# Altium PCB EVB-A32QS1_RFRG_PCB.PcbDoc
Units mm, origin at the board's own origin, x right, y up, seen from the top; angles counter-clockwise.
Board outline 51 x 34 mm, 4 copper layers (L1 (Signal), L2 (GND), L3 (PWR), L4 (Signal)), stack 1.586 mm thick; 35 components, 27 nets, 143 pads, 70 vias.
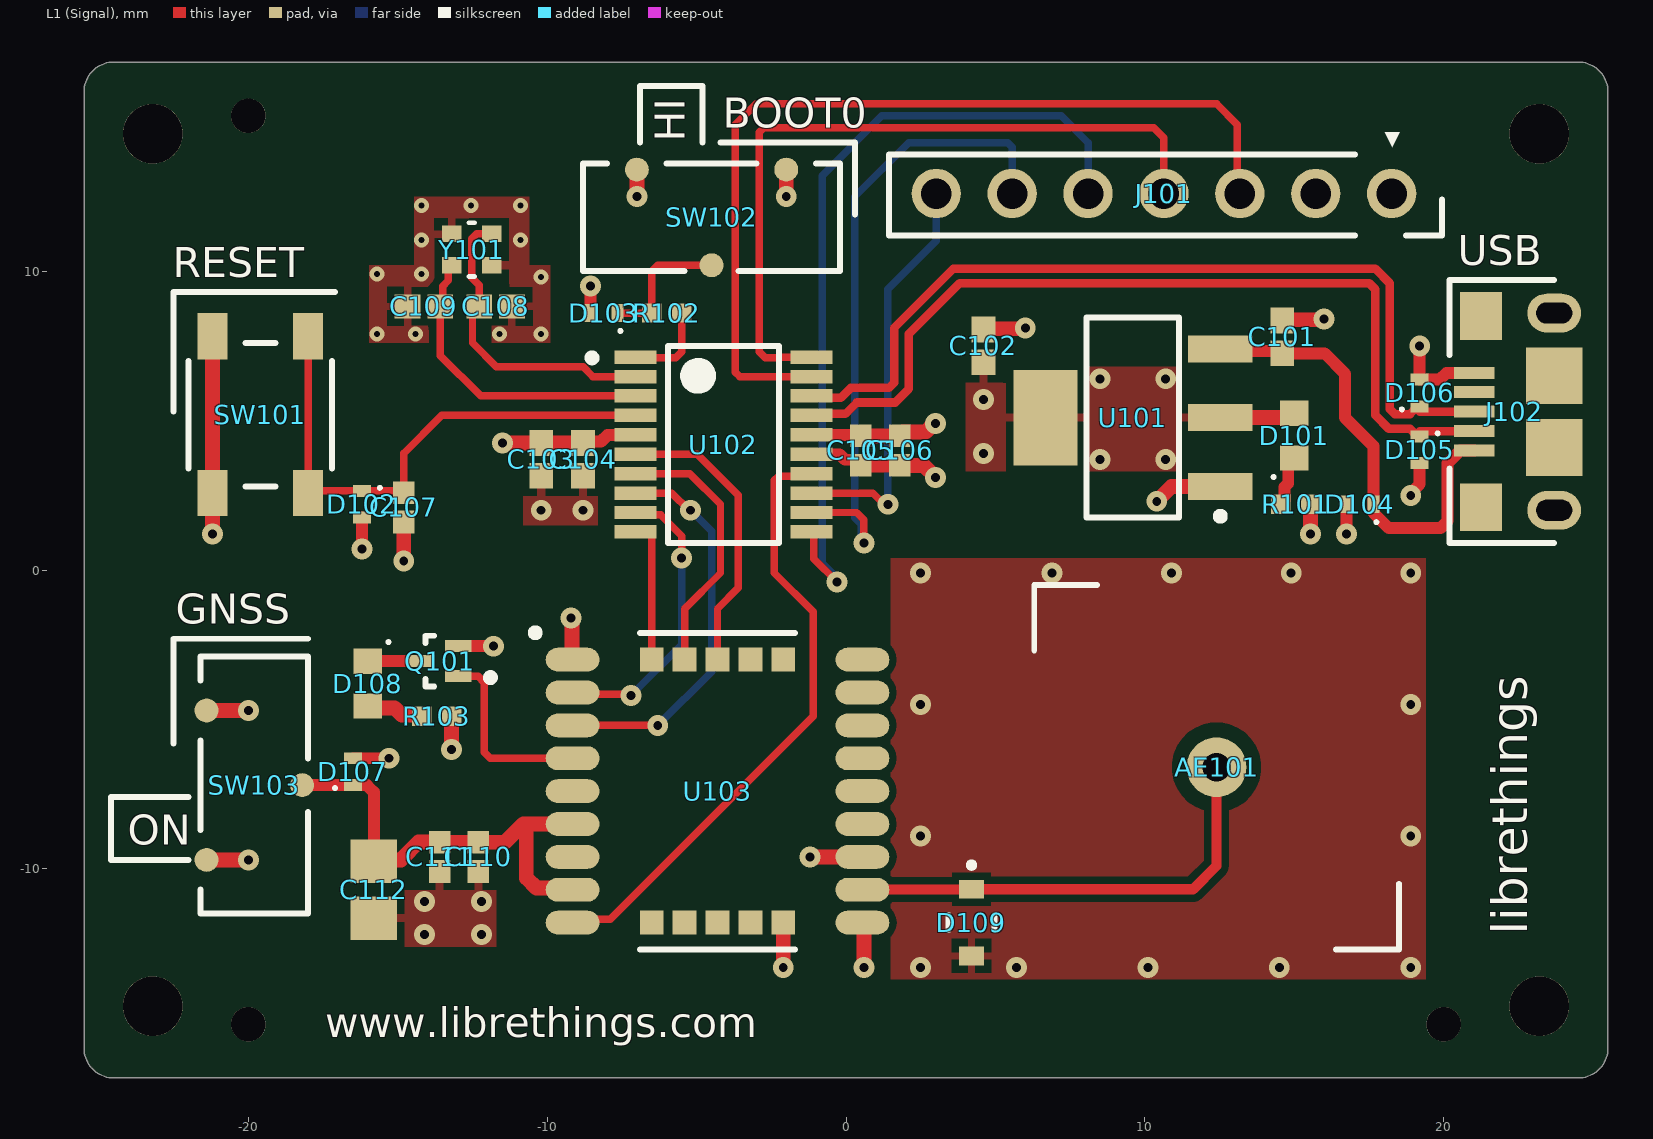
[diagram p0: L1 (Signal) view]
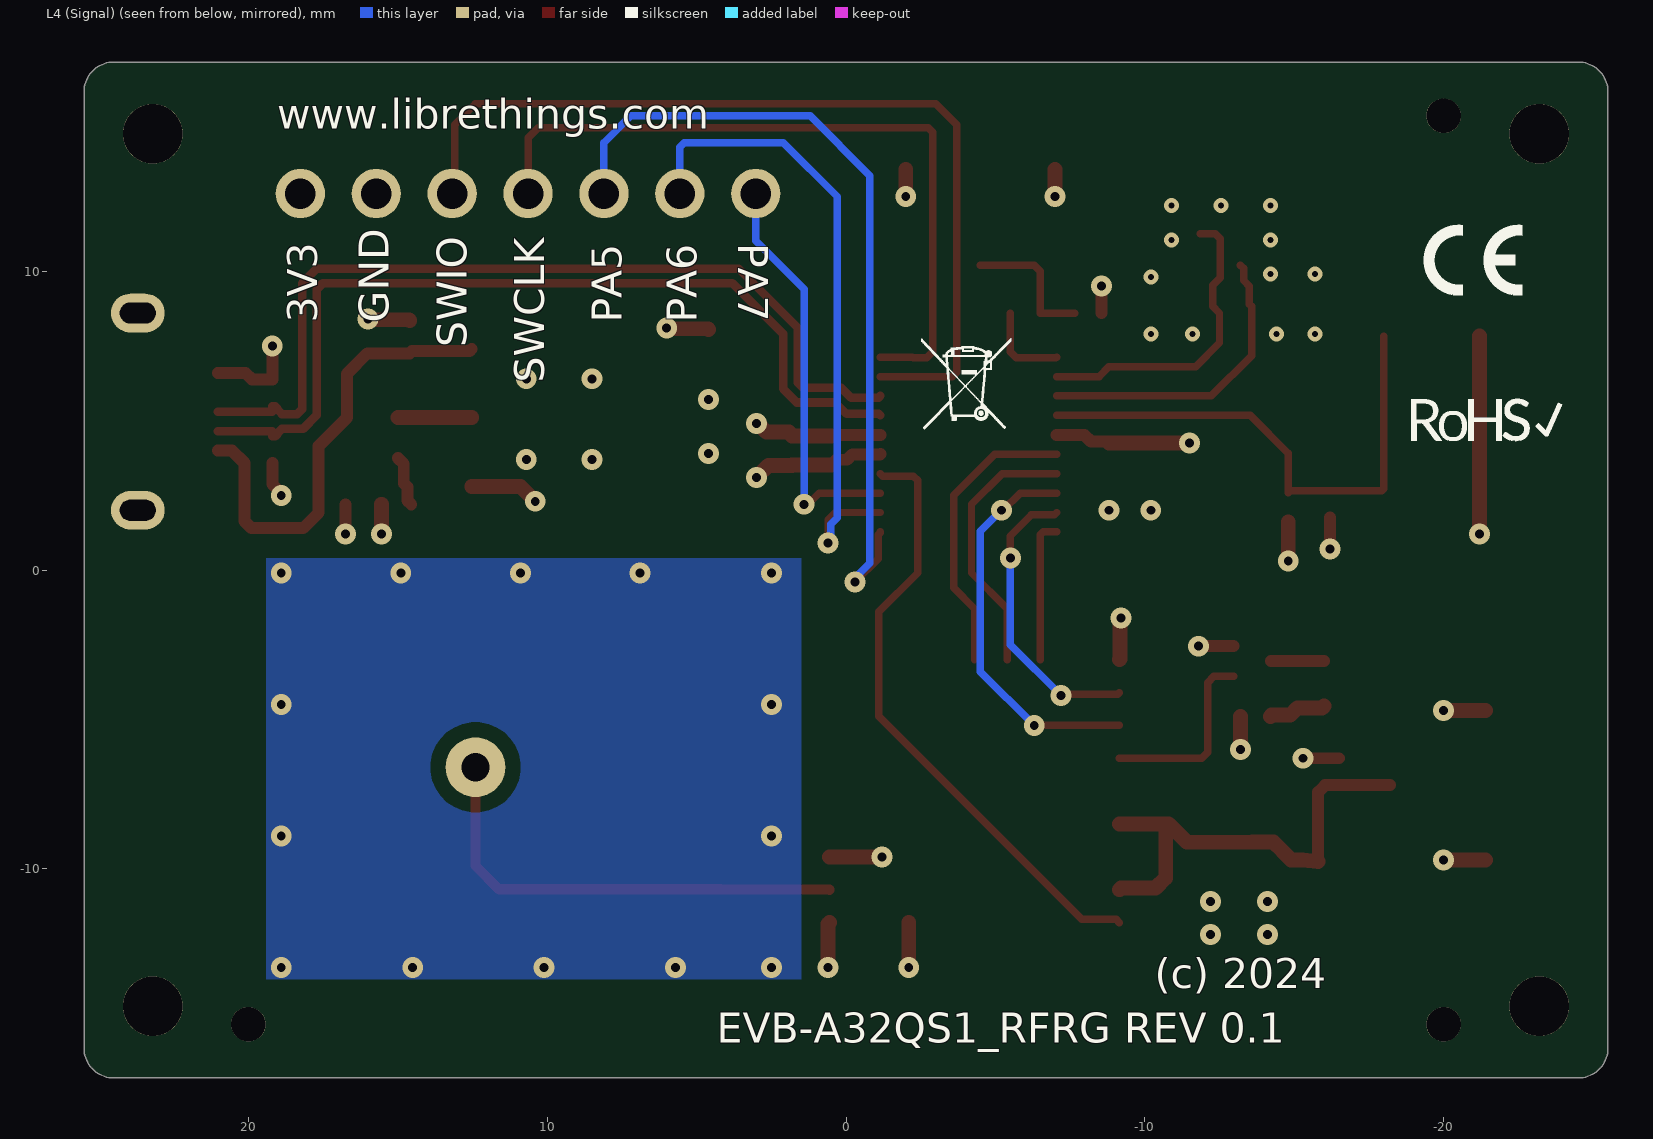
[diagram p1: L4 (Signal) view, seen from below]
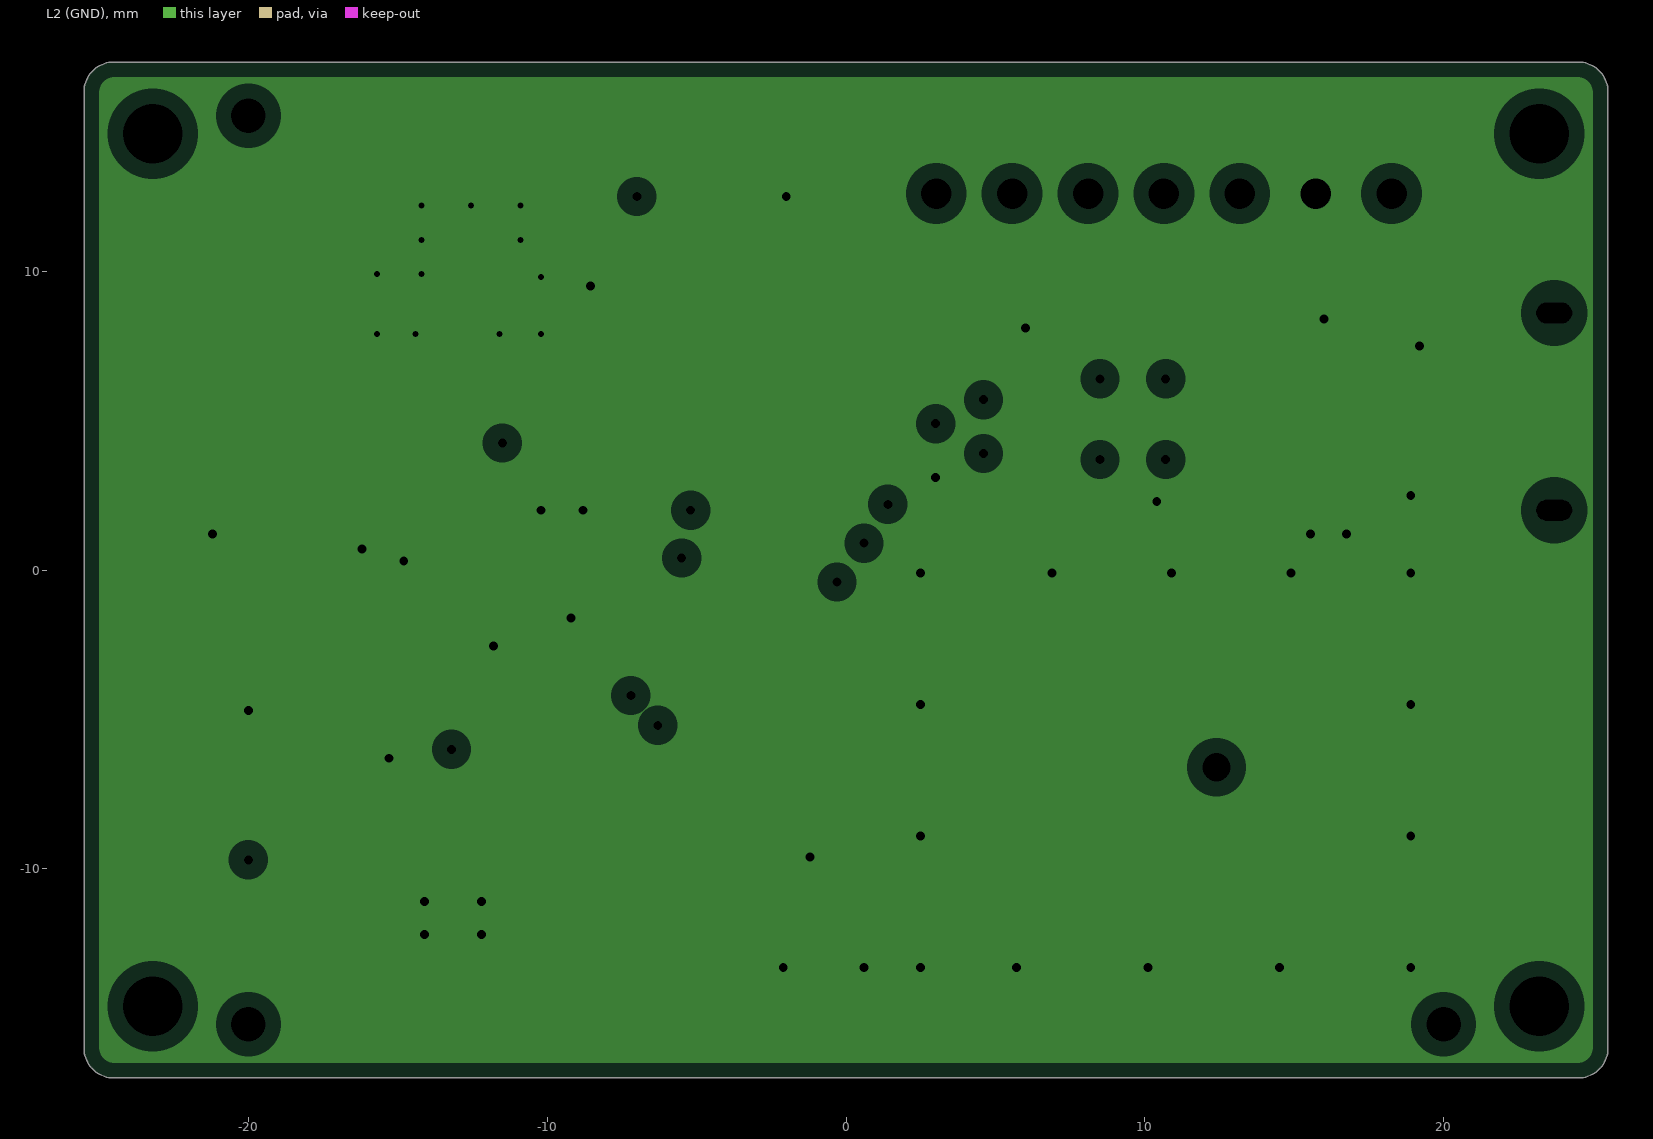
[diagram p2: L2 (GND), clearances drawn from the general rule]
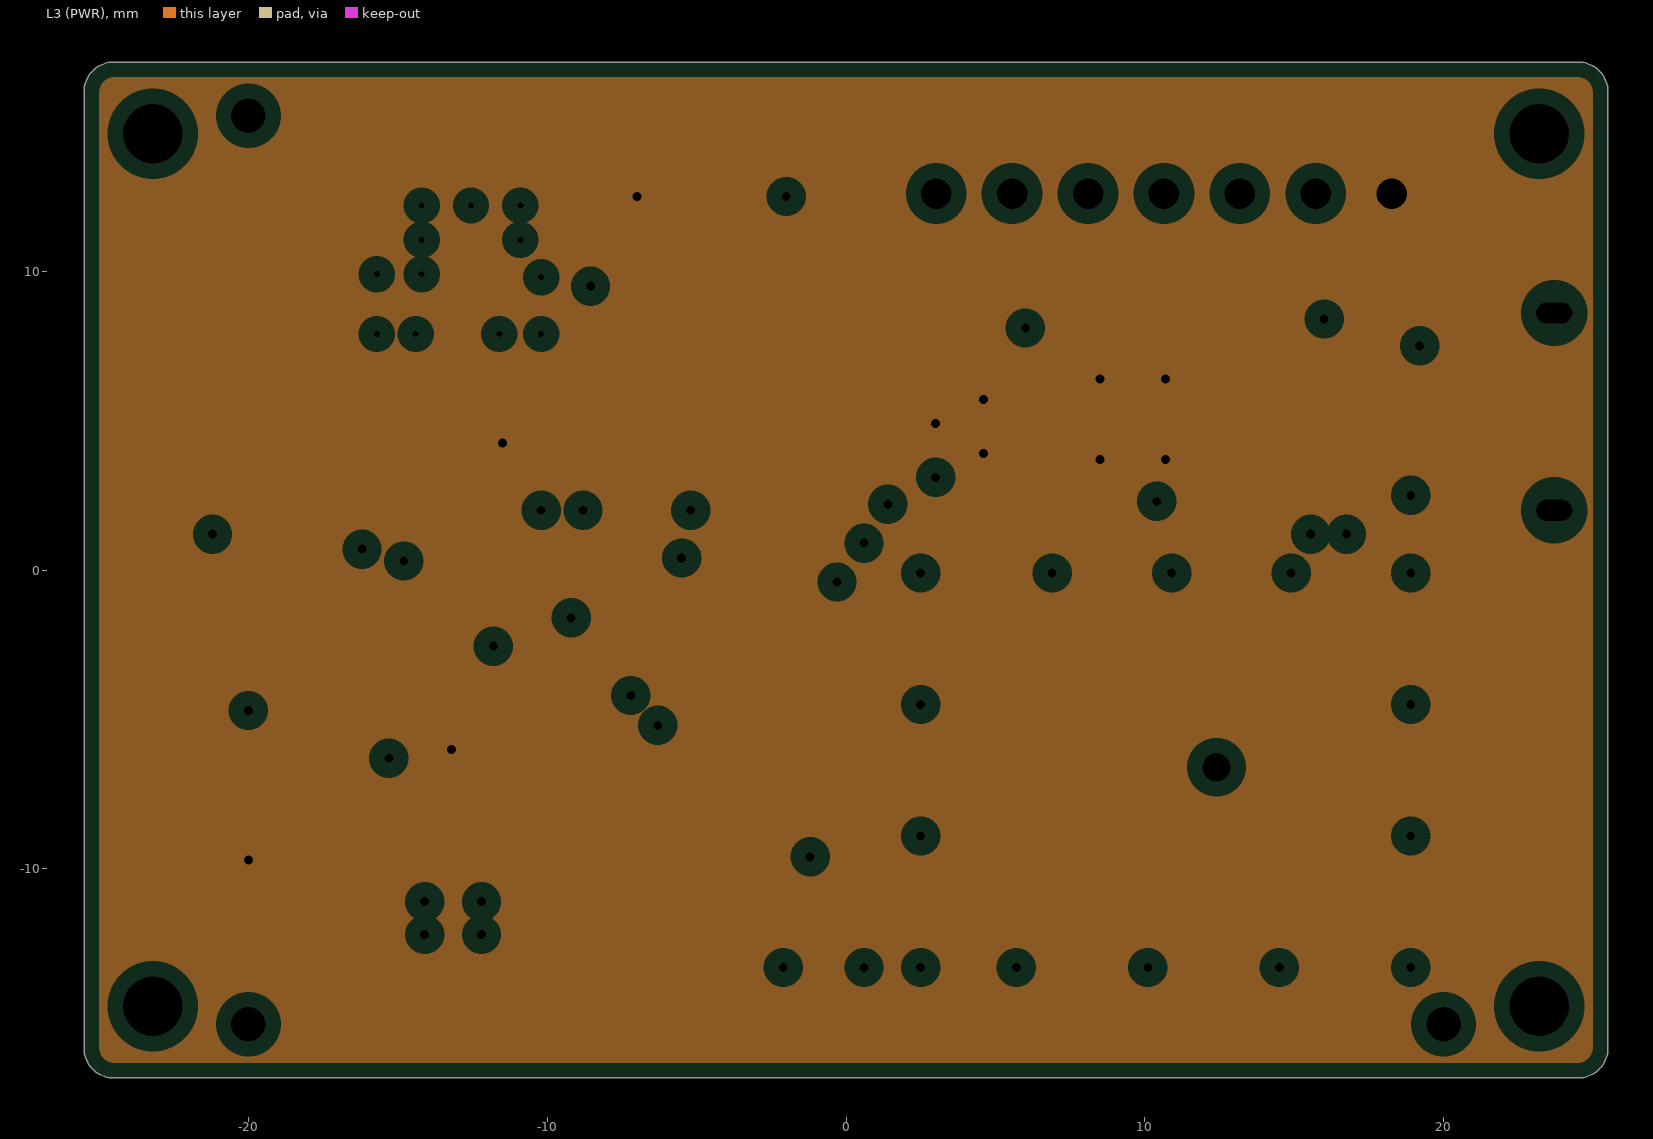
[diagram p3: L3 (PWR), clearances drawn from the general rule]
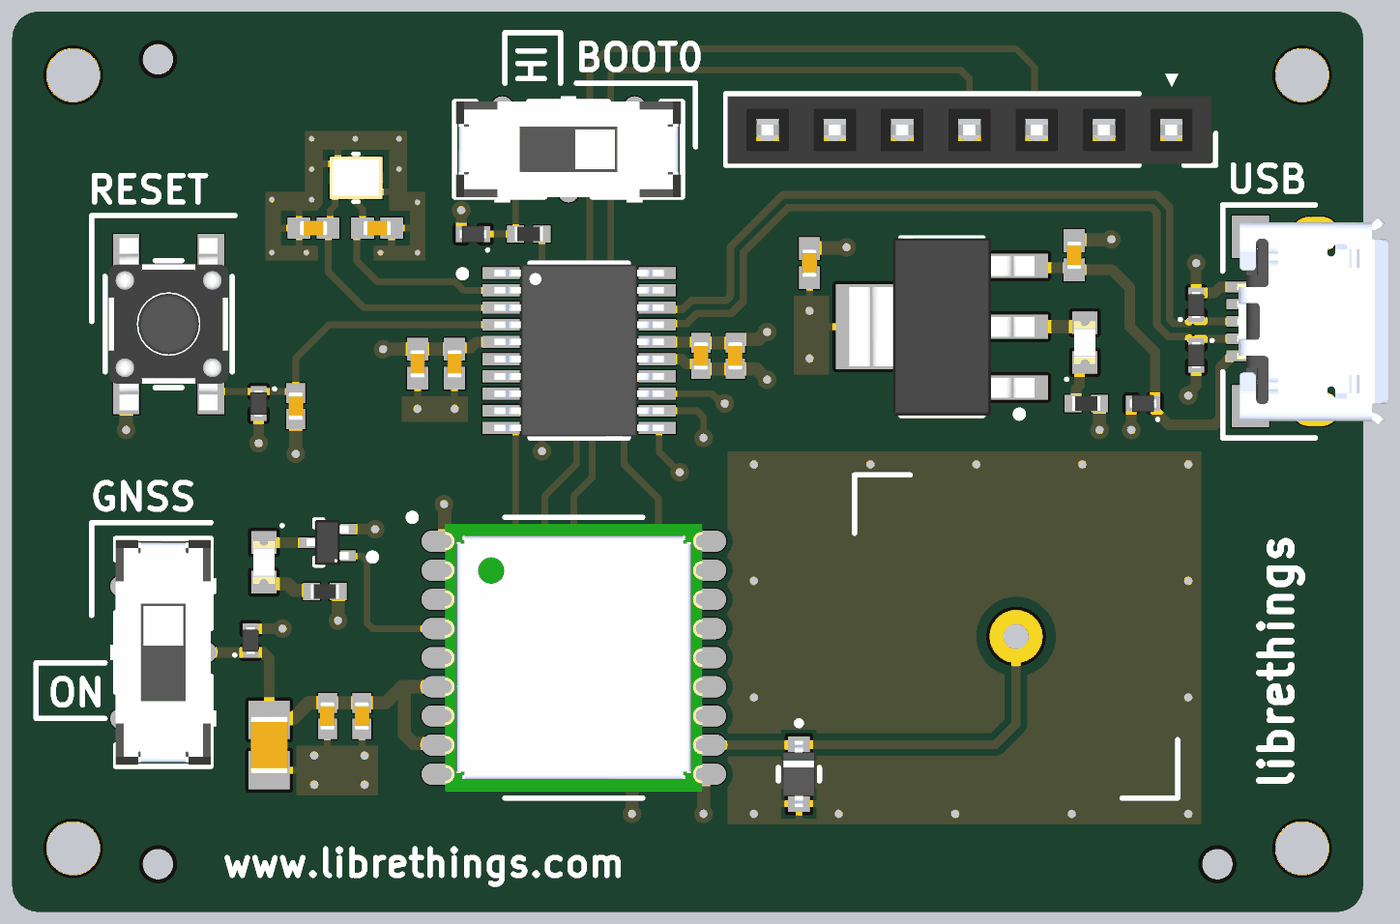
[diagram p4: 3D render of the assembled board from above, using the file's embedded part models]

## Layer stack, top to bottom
Top Solder: solder mask 0.0152, JLC-001, Dk 3.8
L1 (Signal): signal copper 0.035
PP1_7628: prepreg 0.2104, Nan Ya Plastics NP-155F 7628, Dk 4.4
L2 (GND): plane copper 0.0152, net GND
C_FR4: core 1.065, Nan Ya Plastics NP-155F FR4 / 1-7628, Dk 4.6
L3 (PWR): plane copper 0.0152, net +3V3
PP2_7628: prepreg 0.2104, Nan Ya Plastics NP-155F 7628, Dk 4.4
L4 (Signal): signal copper 0.035
Bottom Solder: solder mask 0.0152, JLC-001, Dk 3.8

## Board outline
-25.5,-16 -25.5,16 cw(c-24.5,16) -24.5,17 24.5,17 cw(c24.5,16) 25.5,16 25.5,-16 cw(c24.5,-16) 24.5,-17 -24.5,-17 cw(c-24.5,-16)

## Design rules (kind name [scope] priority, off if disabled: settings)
BoardOutlineClearance [IsText = 'True'] p1: gap=0.3 ignorepadtopadclearanceinfootprint=FALSE
Clearance [All] p1: gap=0.25 ignorepadtopadclearanceinfootprint=FALSE except(0.1: Arc-Arc Arc-Track Track-Track; 0.15: SMDPad-SMDPad; 0.22: Arc-SMDPad Track-SMDPad; 0.27: Arc-Via Arc-Hole Track-Via Track-Hole; 0.5: THPad-THPad)
DiffPairsRouting [InDifferentialPairClass('DIFF_USB')] p1: maxlimit=0.203 minlimit=0.203 mostfreqgap=0.203 toplayer_minwidth=0.286 toplayer_maxwidth=0.286 toplayer_prefwidth=0.286 bottomlayer_minwidth=0.286 bottomlayer_maxwidth=0.286 bottomlayer_prefwidth=0.286 impedanceprofiledriven=TRUE impedanceprofileid={1D80E4EB-765F-47FF-8A09-11E6335E2081} impedanceprofilevalue=90.000000 maxuncoupledlength=12.7
HoleSize NPTHSlotSize [HoleType = 'Slot' && PadIsPlated = 'False'] p1: absolutevalues=TRUE maxlimit=5.6 minlimit=1 maxpercent=80.000 minpercent=20.000
HoleSize PTHSlotSize [HoleType = 'Slot' && PadIsPlated = 'True'] p2: absolutevalues=TRUE maxlimit=5.6 minlimit=0.5 maxpercent=80.000 minpercent=20.000
HoleSize PTHSize [PadIsPlated = 'True'] p3: absolutevalues=TRUE maxlimit=6.35 minlimit=0.2 maxpercent=80.000 minpercent=20.000
HoleSize NPTHSize [PadIsPlated = 'False'] p4: absolutevalues=TRUE maxlimit=6.3 minlimit=0.2 maxpercent=80.000 minpercent=20.000
HoleToHoleClearance [All] p1: gap=0.5 allowstackedmicrovias=TRUE
MinimumAnnularRing PTHSlotMinimumAnnularRing_1 [HoleType = 'Slot' && PadIsPlated = 'True'] p1: minimumring=0.3
MinimumAnnularRing PTHMinimumAnnularRing [PadIsPlated = 'True'] p2: minimumring=0.3
MinimumAnnularRing ViaMinimumAnnularRing [IsVia] p3: minimumring=0.15
MinimumSolderMaskSliver [All] p1: minsoldermaskwidth=0.1
PlaneClearance [All] p1: clearance=0.508
PlaneConnect [All] p1: pad.planeconnectstyle=Relief pad.reliefexpansion=0.508 pad.reliefentries=4 pad.reliefconductorwidth=0.254 pad.reliefairgap=0.254 via.planeconnectstyle=Direct via.reliefexpansion=0.508 via.reliefentries=4 via.reliefconductorwidth=0.254 via.reliefairgap=0.254
PolygonConnect [All] p1: thpad.connectstyle=Relief thpad.reliefconductorwidth=0.254 thpad.reliefentries=4 thpad.polygonreliefangle="90 Angle" thpad.airgapwidth=0.254 smdpad.connectstyle=Relief smdpad.reliefconductorwidth=0.254 smdpad.reliefentries=4 smdpad.polygonreliefangle="90 Angle" smdpad.airgapwidth=0.254 via.connectstyle=Direct via.reliefconductorwidth=0.254 via.reliefentries=4 via.polygonreliefangle="90 Angle" via.airgapwidth=0.254
RoutingVias [All] p1: holewidth=0.3 width=0.7 viastyle="Through Hole" minholewidth=0.2 minwidth=0.5 maxholewidth=0.5 maxwidth=1
SilkToSilkClearance [All] p1: silktosilkclearance=0.3
SilkToSolderMaskClearance [IsPad] p1: minsilkscreentomaskgap=0.15 clearancetoexposedcopper=TRUE
SolderMaskExpansion [All] p1: expansion=0.127 istentingtop=FALSE
SupplyNets "Schematic Supply Nets_6" [InNet('+3V3_GNSS')] p1: voltage=0.000
SupplyNets "Schematic Supply Nets_5" [InNet('VBUS')] p2: voltage=0.000
SupplyNets "Schematic Supply Nets_4" [InNet('GND')] p3: voltage=0.000
SupplyNets "Schematic Supply Nets" [InNet('+3V3')] p4: voltage=0.000
UnRoutedNet [All] p1: checkbadconnections=TRUE
Width AE50 [InNetClass('AE50')] p1: maxlimit=0.342 minlimit=0.342 preferedwidth=0.342 impedanceprofiledriven=TRUE impedanceprofileid={35CBA2D1-E87A-4068-99C0-F5B5DE871103} impedanceprofilevalue=50.000000 minimp=50.000000 maximp=50.000000 favimp=50.000000
Width [All] p2: maxlimit=0.5 minlimit=0.1 preferedwidth=0.25
21 further rules are at their usual default settings.

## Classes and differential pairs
differential pair class DIFF_USB: USB_D
net class AE50: GNSS_RF_IN
differential pair USB_D: +USB_D_P -USB_D_N

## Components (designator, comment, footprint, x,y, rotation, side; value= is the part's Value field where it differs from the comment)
AE101 "YCGA002AA" AE_Quectel_YCGA002AA 12.4,-6.6 r0 top locked
C101 "CC0402MRX5R6BB105" C_Yageo_CC_0402_A 14.6,7.8 r270 top value=1uF
C102 "CC0402MRX5R6BB105" C_Yageo_CC_0402_A 4.6,7.5 r270 top value=1uF
C103 "CC0402MRX5R6BB105" C_Yageo_CC_0402_A -10.2,3.7 r90 top value=1uF
C104 "CC0402KRX7R7BB103" C_Yageo_CC_0402_A -8.8,3.7 r90 top value=10nF
C105 "CL05B104KP5NNNC" C_Samsung_CL_0402_A 0.5,4 r90 top value=100nF
C106 "CL05A475MP5NRNC" C_Samsung_CL_0402_A 1.8,4 r90 top value=4.7uF
C107 "CL05B104KP5NNNC" C_Samsung_CL_0402_A -14.8,2.1 r90 top value=100nF
C108 "CC0402JRNPO9BN150" C_Yageo_CC_0402_A -11.725,8.825 r180 top value=15pF
C109 "CC0402JRNPO9BN150" C_Yageo_CC_0402_A -14.125,8.825 r0 top value=15pF
C110 "CL05C330JB5NNNC" C_Samsung_CL_0402_A -12.3,-9.6 r90 top value=33pF
C111 "CL05B104KP5NNNC" C_Samsung_CL_0402_A -13.6,-9.6 r90 top value=100nF
C112 "CL21A106KOQNNNE" C_Samsung_CL_0805_A -15.8,-10.7 r90 top value=10uF
D101 "LTST-C190GKT" D_LED_Lite-On_Green_0603_A 15,4.5 r90 top
D102 "D5V0F1U2S9-7" D_TVS_Uni_Diodes_SOD-923_B -16.2,2.2 r270 top value=5E-13F
D103 "D5V0F1U2S9-7" D_TVS_Uni_Diodes_SOD-923_B -8.1,8.6 r180 top value=5E-13F
D104 "D5V0F1U2S9-7" D_TVS_Uni_Diodes_SOD-923_B 17.2,2.2 r180 top value=5E-13F
D105 "D5V0F1U2S9-7" D_TVS_Uni_Diodes_SOD-923_B 19.2,4.025 r270 top value=5E-13F
D106 "D5V0F1U2S9-7" D_TVS_Uni_Diodes_SOD-923_B 19.2,5.925 r90 top value=5E-13F
D107 "D5V0F1U2S9-7" D_TVS_Uni_Diodes_SOD-923_B -16.5,-6.75 r90 top value=5E-13F
D108 "LTST-C190GKT" D_LED_Lite-On_Green_0603_A -16,-3.8 r270 top
D109 "ESD7351HT1G" D_TVS_Uni_Onsemi_SOD-323 4.2,-11.8 r270 top
J101 "PPPC071LFBN-RC" J_Sullins_01x07_Socket_2.54mm 10.64,12.6 r180 top
J102 "10118193-0001LF" J_USB_Micro-B_Amphenol_10118193-0001LF 23.7,5.3 r90 top
Q101 "DTC043ZEBTL" Q_Rohm_SOT-416FL_B -13.6,-3.05 r180 top
R101 "RC0402FR-071KL" R_Yageo_RCL_0402_A 15.05,2.2 r180 top value=1kR
R102 "RC0402FR-0710KL" R_Yageo_RCL_0402_A -6,8.6 r0 top value=10kR
R103 "RC0402FR-071KL" R_Yageo_RCL_0402_A -13.7,-4.9 r0 top value=1kR
SW101 "PTS647SN50SMTR2LFS" SW_Tactitle_SPST_C&K_PTS647SN50SMTR2LFS -19.6,5.2 r270 top
SW102 "JS102011JCQN" SW_Slide_C&K_JS102011JCQN -4.5,11.8 r180 top
SW103 "JS102011JCQN" SW_Slide_C&K_JS102011JCQN -19.8,-7.2 r270 top
U101 "TLV1117LV33DCYR" U_TI_SOT-223_B 9.6,5.1 r180 top
U102 "STM32F070F6P6TR" U_ST_TSSOP20_B -4.1,4.2 r0 top
U103 "LC76GABMD" U_QUECTEL_LC76G -4.3,-7.4 r0 top
Y101 "ECS-240-12-37B-CKY-TR" Y_Crystal_GND24_ECS_240-12-37B-CKY-TR -12.525,10.725 r180 top

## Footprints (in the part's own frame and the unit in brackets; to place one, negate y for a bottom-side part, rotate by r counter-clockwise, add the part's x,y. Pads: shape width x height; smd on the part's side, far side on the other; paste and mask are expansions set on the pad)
AE_Quectel_YCGA002AA [mm]
  round 2 hole 0.95: 1(0,0)
  silkscreen extent -6.1,-6.1 6.1,6.1, body extent -6,-6 6,6, height 4
C_Samsung_CL_0402_A [mm] "Chip Capacitor, 2-Leads, Body 1.00x0.50mm, IPC Low Density"
  rect 0.76x0.72 smd mask+0.05: 1(-0.49,0) 2(0.49,0)
  body extent -0.53,-0.28 0.53,0.28, height 0.55
C_Samsung_CL_0805_A [mm] "Chip Capacitor, 2-Leads, Body 2.00x1.25mm, IPC Low Density"
  rect 1.45x1.55 smd: 1(-0.95,0) 2(0.95,0)
  body extent -1.07,-0.7 1.07,0.7, height 1.4
C_Yageo_CC_0402_A [mm] "Yageo series CC Chip Capacitor, 2-Leads, Body 1.00x0.50mm, IPC Low Density"
  rect 0.86x0.8 smd mask+0.05: 1(-0.55,0) 2(0.55,0)
  body extent -0.53,-0.28 0.53,0.28, height 0.7
D_LED_Lite-On_Green_0603_A [mm] "Chip Diode, 2-Leads, Body 1.60x0.70mm, IPC Low Density"
  rect 0.85x0.95 smd: 1(-0.75,0) 2(0.75,0)
  silkscreen extent -1.44,0.64 -1.34,0.74, body extent -0.8,-0.4 0.8,0.4, height 0.8
D_TVS_Uni_Diodes_SOD-923_B [mm] "SODFL, 2-Leads, Body 0.60x1.00mm, IPC Medium Density"
  rect 0.4x0.6 smd: 1(-0.45,0) 2(0.45,0)
  silkscreen extent -0.6,0.55 -0.5,0.65, body extent -0.5,-0.33 0.5,0.33, height 0.4
D_TVS_Uni_Onsemi_SOD-323 [mm]
  rect 0.63x0.83 smd: 1(-1.115,0) 2(1.115,0)
  silkscreen extent -2.02,-0.77 0.25,0.77, body extent -1.25,-0.62 1.25,0.62, height 1
J_Sullins_01x07_Socket_2.54mm [mm]
  round 1.65 hole 1.02 mask+0.05: 1(-7.62,0) 2(-5.08,0) 3(-2.54,0) 4(0,0) 5(2.54,0) 6(5.08,0) 7(7.62,0)
  silkscreen extent -9.3,-1.3 9.2,1.4, body extent -9.14,-1.2 9.14,1.34, height 8.5
J_USB_Micro-B_Amphenol_10118193-0001LF [mm] "USB - micro B USB 2.0 Receptacle Connector 5 Position Surface Mount, Right Angle; Through Hole"
  rect 0.4x1.35 smd mask+0.05: 1(-1.3,2.675) 2(-0.65,2.675) 3(0,2.675) 4(0.65,2.675) 5(1.3,2.675)
  rect 1.6x1.4 smd mask+0.05: 6(-3.2,2.45) 7(3.2,2.45)
  rect 1.9x1.9 smd mask+0.05: 8(1.2,0) 9(-1.2,0)
  oval 1.3x1.8 hole 0.7 slot 1.2 at 90 deg mask+0.05: 10(3.3,0) 11(-3.3,0)
  silkscreen extent -4.4,0 4.4,3.5, body extent -3.93,-2.76 3.93,2.95, height 2.81
Q_Rohm_SOT-416FL_B [mm] "SOTFL, 3-Leads, Body 1.60x1.60mm, Pitch 0.50mm, IPC Medium Density"
  rect 0.9x0.4 smd mask+0.05: 1(-0.625,0.5) 2(-0.625,-0.5) 3(0.625,0)
  silkscreen extent -1.83,-0.85 0.48,0.85, body extent -0.8,-0.85 0.8,0.85, height 0.85
R_Yageo_RCL_0402_A [mm] "Yageo series RC_L Chip Resistor, 2-Leads, Body 1.00x0.50mm, IPC Low Density"
  rect 0.65x0.65 smd mask+0.05: 1(-0.5,0) 2(0.5,0)
  body extent -0.53,-0.28 0.53,0.28, height 0.4
SW_Slide_C&K_JS102011JCQN [mm] "Slide Switch SPDT Surface Mount"
  round 0.8 smd mask+0.05: 1(-2.5,-1.6) 2(0,1.6) 3(2.5,-1.6)
  silkscreen extent -4.3,-1.8 4.3,1.8, body extent -4.25,-2 4.25,2, height 5.4
SW_Tactitle_SPST_C&K_PTS647SN50SMTR2LFS [mm] "Tactitle switch SPST-NO 4.5mm x 4.5mm"
  rect 1.55x1 smd mask+0.05: 1(-2.625,1.6) 2(2.625,1.6) 3(-2.625,-1.6) 4(2.625,-1.6)
  silkscreen extent -2.4,-2.4 2.4,2.4, body extent -3.25,-2.25 3.25,2.25, height 5
U_QUECTEL_LC76G [mm]
  oval 1.8x0.8 smd mask+0.05: 1(-4.85,4.4) 2(-4.85,3.3) 3(-4.85,2.2) 4(-4.85,1.1) 5(-4.85,0) 6(-4.85,-1.1) 7(-4.85,-2.2) 8(-4.85,-3.3) 9(-4.85,-4.4) 10(4.85,-4.4) 11(4.85,-3.3) 12(4.85,-2.2) 13(4.85,-1.1) 14(4.85,0) 15(4.85,1.1) 16(4.85,2.2) 17(4.85,3.3) 18(4.85,4.4)
  rect 0.8x0.8 smd mask+0.05: 19(2.2,4.4) 20(1.1,4.4) 21(0,4.4) 22(-1.1,4.4) 23(-2.2,4.4) 24(-2.2,-4.4) 25(-1.1,-4.4) 26(0,-4.4) 27(1.1,-4.4) 28(2.2,-4.4)
  silkscreen extent -6.22,-5.3 2.6,5.42, body extent -4.85,-5.05 4.85,5.05, height 2.66
U_ST_TSSOP20_B [mm] "TSOP, 20-Leads, Body 6.50x4.40mm, Pitch 0.65mm, IPC Medium Density"
  rect 1.4x0.45 smd mask+0.05: 1(-2.95,2.925) 2(-2.95,2.275) 3(-2.95,1.625) 4(-2.95,0.975) 5(-2.95,0.325) 6(-2.95,-0.325) 7(-2.95,-0.975) 8(-2.95,-1.625) 9(-2.95,-2.275) 10(-2.95,-2.925) 11(2.95,-2.925) 12(2.95,-2.275) 13(2.95,-1.625) 14(2.95,-0.975) 15(2.95,-0.325) 16(2.95,0.325) 17(2.95,0.975) 18(2.95,1.625) 19(2.95,2.275) 20(2.95,2.925)
  silkscreen extent -4.52,-3.3 1.85,3.3, body extent -3.2,-3.25 3.2,3.25, height 1.2
U_TI_SOT-223_B [mm] "SOT223, 4-Leads, Body 6.50x7.00mm (avg), Pitch 2.30mm, IPC Medium Density"
  rect 2.15x0.9 smd: 1(-2.925,2.3) 2(-2.925,0) 3(-2.925,-2.3)
  rect 2.15x3.2 smd: 4(2.925,0)
  silkscreen extent -3.05,-3.35 1.55,3.42, body extent -3.5,-3.35 3.5,3.35, height 1.8
Y_Crystal_GND24_ECS_240-12-37B-CKY-TR [mm]
  rect 0.65x0.55 smd mask+0.05: 1(-0.675,-0.525) 2(0.675,-0.525) 3(0.675,0.525) 4(-0.675,0.525)
  silkscreen extent -0.1,-0.9 0.1,0.9, body extent -1,-0.8 1,0.8, height 0.51

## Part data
AE101: library part CMP-00025-00001-2, "Antenna Module Linear 1602MHz", Frequency (Center/Band)=1.5825GHz, Frequency Group="UHF (1GHz ~ 2GHz)", Frequency Range="1.559GHz ~ 1.606GHz", Manufacturer=Quectel
C101 C102 C103: library part CMP-001-00016-11, "Multilayer Ceramic Capacitor, 1 uF, 50 V, ± 10%, X5R, 0402 [1005 Metric]", Case Code (Imperial)=0402, Case Code (Metric)=1005, Dielectric=X5R, LCSC Part Number=C113791, Max Operating Temperature=85°C, Min Operating Temperature=-55°C, Temperature Coefficient=30ppm/°C, Tolerance=20%, Voltage Rating=10V
C104: library part CMP-001-00029-1, "Multilayer Ceramic Capacitor, 0.01 uF, 16 V, ± 10%, X7R, 0402 [1005 Metric]", Case Code (Imperial)=0402, Case Code (Metric)=1005, Dielectric=X7R, Insulation Resistance=10GR, Max Operating Temperature=125°C, Min Operating Temperature=-55°C, Package Quantity=1, Temperature Coefficient=30ppm/°C, Tolerance=10%, Voltage Rating=16V
C105 C107 C111: library part CMP-001-00023-3, "Multilayer Ceramic Capacitor, 0.1 uF, 10 V, ± 10%, X7R, 0402 [1005 Metric]", Case Code (Imperial)=0402, Case Code (Metric)=1005, Dielectric=X7R, Max Operating Temperature=125°C, Min Operating Temperature=-55°C, Package Quantity=1, Tolerance=10%, Voltage Rating=10V
C106: library part CMP-001-00024-3, "Multilayer Ceramic Capacitor, 4.7 uF, 10 V, ± 20%, X5R, 0402 [1005 Metric]", Case Code (Imperial)=0402, Case Code (Metric)=1005, Dielectric=X5R, Max Operating Temperature=85°C, Min Operating Temperature=-55°C, Tolerance=20%, Voltage Rating=10V
C108 C109: library part CMP-001-00017-14, "Multilayer Ceramic Capacitor, 15 pF, 10 V, ± 5%, X7R, 0402 [1005 Metric]", Case Code (Imperial)=0402, Case Code (Metric)=1005, Dielectric=C0G, Dielectric Material=Ceramic, Insulation Resistance=100GR, Max Operating Temperature=125°C, Min Operating Temperature=-55°C, Package Quantity=1, Temperature Coefficient=30ppm/°C, Tolerance=5%, Voltage=50V
C110: library part CMP-001-00030-2, "Multilayer Ceramic Capacitor, 33 pF, 50 V, ± 5%, C0G (NP0), 0402 [1005 Metric]", Case Code (Imperial)=0402, Case Code (Metric)=1005, Dielectric=C0G, Max Operating Temperature=125°C, Min Operating Temperature=-55°C, Package Quantity=1, Temperature Coefficient=300ppm/°C, Tolerance=5%, Voltage=50V
C112: library part CMP-001-00022-4, "Multilayer Ceramic Capacitor, 10 uF, 16 V, ± 10%, X5R, 0805 [2012 Metric]", Case Code (Imperial)=0805, Case Code (Metric)=2012, Dielectric=X7R, Max Operating Temperature=85°C, Min Operating Temperature=-55°C, Package Quantity=1, Tolerance=10%, Voltage=16V
D101 D108: library part CMP-007-00001-3, "LED Uni-Color Green 565nm 2-Pin Chip LED T/R", Case Code (Imperial)=0603, Case Code (Metric)=1608, Color=Green, Forward Current=30mA, Forward Voltage=2.1V, Lens Color=Colorless, Max Operating Temperature=85°C, Min Operating Temperature=-55°C, Package Quantity=1, Power Dissipation=100mW, Reverse Voltage=5V, Test Current=10mA, Voltage=2V
D102 D103 D104 D105 D106 D107: library part CMP-004-00007-2, "Diode TVS Dual Uni-Dir 5.5V 250000W 2-Pin SOD-923 T/R", Breakdown Voltage=6V, Case/Package=SOD-923-2, Clamping Voltage=10V, Max Operating Temperature=150°C, Max Power Dissipation=250mW, Max Reverse Leakage Current=100nA, Max Surge Current=1.5A, Min Operating Temperature=-65°C, Package Quantity=10000, Peak Pulse Power=250kW, Power Line Protection=Yes, Reverse Standoff Voltage=5.5V
D109: library part CMP-004-00006-1, "TVSDIODE3.3VWMSOD-323", Case/Package=SOD, Max Operating Temperature=150°C, Min Breakdown Voltage=5V, Min Operating Temperature=-55°C, Package Quantity=3000, Power Line Protection=No, Reverse Standoff Voltage=3.3V
J101: library part CMP-002-00007-1, "Conn Hdr 7POS 0.1 Gold Pcb", Flammability Rating="UL94 V-0", Insulation Color=Black, Max Operating Temperature=105°C, Min Operating Temperature=-40°C, Voltage Rating=250V
J102: library part CMP-002-00002-12, "Usb Connector, 5 Contact(S), Female, Right Angle, Surface Mount Terminal, Locking, Receptacle", Color=Black, Current Rating=1.8A, Flammability Rating="UL94 V-0", Insulation Resistance=1GR, Max Operating Temperature=85°C, Max Voltage Rating (AC)=100V, Min Operating Temperature=-55°C, Package Quantity=1200
Q101: library part CMP-013-00001-2, "TRANS PREBIAS NPN 50V EMT3F", Clock Frequency=250MHz, Collector Emitter Breakdown Voltage=50V, Collector-emitter Voltage-Max=150mV, Continuous Collector Current=100mA, Max Operating Temperature=150°C, Max Power Dissipation=150mW, Min Operating Temperature=-55°C, Output Voltage=50mV, Package Quantity=3000
R101 R103: library part CMP-009-00002-11, "SMD Chip Resistor, 1 kOhm, ± 1%, 62.5 mW, 0402 [1005 Metric], Thick Film, General Purpose", Case Code (Imperial)=0402, Case Code (Metric)=1005, Max Operating Temperature=155°C, Max Power Dissipation=63mW, Min Operating Temperature=-55°C, Power Rating=62.5mW, Resistance Tolerance=1%, Resistor Type="Thick Film", Temperature Coefficient=100ppm/°C, Voltage Rating=50V
R102: library part CMP-009-00003-11, "SMD Chip Resistor, 10 kOhm, ± 1%, 62.5 mW, 0402 [1005 Metric], Thick Film, General Purpose", Case Code (Imperial)=0402, Case Code (Metric)=1005, Max Operating Temperature=155°C, Max Power Dissipation=63mW, Min Operating Temperature=-55°C, Power Rating=62.5mW, Resistance Tolerance=1%, Resistor Type="Thick Film", Temperature Coefficient=100ppm/°C, Voltage Rating=50V
SW101: library part CMP-011-00000-13, "Switch Tactile N.O. SPST Round Button Gull Wing 0.05A 12VDC 100000Cycles 0.98N SMD T/R", Max Operating Temperature=70°C, Min Operating Temperature=-20°C, Operating Force=100gf, Ratings=IP40
SW102 SW103: library part CMP-011-00001-10, "JS Series Sub-Miniature Slide Switch SPDT On-On Top Slide 0.3A 6VDC J-Lead Surface Mount T/R", Max Operating Temperature=85°C, Min Operating Temperature=-40°C, Voltage Rating (DC)=6V
U101: library part CMP-019-00002-2, "LDO Regulator Pos 3.3V 1A 4-Pin(3+Tab) SOT-223 T/R", Case/Package=SOT-223-4, Dropout Voltage=570mV, Max Operating Temperature=125°C, Max Output current=1A, Max Output Voltage=3.3V, Max Supply Voltage=5.5V, Min Input Voltage=2V, Min Operating Temperature=-40°C, Operating Supply Current=50uA, Package Quantity=2500, Power Supply Rejection Ratio (PSRR)=75dB
U102: library part CMP-020-00001-4, "IC MCU 32BIT 32KB FLASH 20TSSOP", Case/Package=TSSOP, Max Operating Temperature=85°C, Min Operating Temperature=-40°C
U103: library part CMP-00025-00000-4, "Navigation BeiDou, Galileo, GLONASS, GPS, GNSS Transceiver Module 1.561GHz, 1.575GHz, 1.602GHz Antenna Not Included Surface Mount", Frequency="1.561GHz, 1.575GHz, 1.602GHz", Package="28-SMD Module", Supply Voltage="2.55V ~ 3.6V"
Y101: library part CMP-003-00000-11, "Crystal 24MHz ±10ppm (Tol) ±10ppm (Stability) 12pF FUND 50Ohm 4-Pin Mini-CSMD T/R", Case/Package="4-SMD, No Lead", Frequency=24MHz, Load Capacitance=12pF

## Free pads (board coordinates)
  round 2 hole 2: MH1(-23.2,14.6) MH2(23.2,14.6) MH3(-23.2,-14.6) MH4(23.2,-14.6)
  round 1.152 hole 1.152 unplated mask+0.148: TH1(-20,15.2) TH2(-20,-15.2) TH3(20,-15.2)

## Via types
v1: diameter 0.7, hole 0.3, L1 (Signal) to L4 (Signal), tented both sides, 58 vias
v2: diameter 0.5, hole 0.2, L1 (Signal) to L4 (Signal), tented both sides, 12 vias

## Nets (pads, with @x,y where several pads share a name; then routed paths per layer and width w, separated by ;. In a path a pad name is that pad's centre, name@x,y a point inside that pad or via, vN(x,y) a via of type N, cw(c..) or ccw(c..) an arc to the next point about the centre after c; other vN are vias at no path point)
3V3_LED_K: D101.1 R101.2 | length 1.7
  L1 (Signal) w0.4: R101.2 14.674,2.324 14.674,2.774 14.8,2.9 14.8,3.55 D101.1
+3V3: C102.2 C103.2 C104.2 C105.2 C106.2 D101.2 J101.1 R103.2 SW102.3 SW103.3 U101.2 U101.4 U102.5 U102.16 | length 14.8
  L1 (Signal) w0.4: C104.2 -8.75,4.3 -8.2,4.3 -7.98,4.52 -7.055,4.52 U102.5 ; U102.16 -1.145,4.52 0.47,4.52 C105.2
  L1 (Signal) w0.5: SW103.3 v1(-20,-9.7) ; v1(-13.2,-6) R103.2 ; v1@-11.5,4.3 ccw(c-11.45,4.3) -11.45,4.25 C103.2 C104.2 ; v1(-7,12.5) SW102.3 ; C105.2 C106.2 1.91,4.6 1.91,4.62 2.666,4.62 2.946,4.9 v1(3,4.9) ; U101.2 D101.2@15,5.1
  other v1: 8.5,3.7 10.7,3.7 4.6,3.9 -11.5,4.25 4.6,5.7 8.5,6.4 10.7,6.4
+3V3_GNSS: C110.2 C111.2 C112.2 D107.1 SW103.2 U103.6 U103.8 | length 15.5
  L1 (Signal) w0.4: SW103.2 -16.6,-7.2 -16.034,-7.2 -15.8,-7.434 C112.2
  L1 (Signal) w0.5: C112.2 -15.275,-9.7 -14.893,-9.7 -14.6,-9.407 -14.6,-9.4 -14.3,-9.1 -13.61,-9.1 C111.2 C110.2 -11.41,-9.11 -10.8,-8.5 ; U103.8 -9.207,-10.643 -10.357,-10.643 -10.7,-10.3 -10.7,-8.6 -10.8,-8.5 ; U103.6 -10.8,-8.5
BOOT0: R102.2 U102.1 | length 2.9
  L1 (Signal) w0.25: U102.1 -7.025,7.1 -5.7,7.1 -5.5,7.3 R102.2
GND: C101.1 C102.1 C103.1 C104.1 C105.1 C106.1 C107.1 C108.1 C109.1 C110.1 C111.1 C112.1 D102.2 D103.2 D104.2 D105.2 D106.2 D107.2 D109.2 J101.2 J102.5 Q101.2 R101.1 SW101.3 SW101.4 SW102.1 SW103.1 U101.1 U102.15 U103.1 U103.10 U103.12 U103.28 Y101.2 Y101.4 | length 36.5
  L1 (Signal) w0.4: D107.2 v1(-15.3,-6.3) ; v1(-16.2,0.7) D102.2 ; Q101.2 -11.85,-2.55 v1@-11.8,-2.5 ; D103.2 -8.55,9.45 v1@-8.5,9.5 ; U102.15 -1.145,3.87 -0.214,3.87 -0.034,3.69 C105.1@0.34,3.69 ; D104.2 16.75,1.25 v1@16.8,1.2 ; v1(18.9,2.5) 18.9,2.573 19.2,2.873 D105.2 ; v1(19.2,7.5) D106.2 19.875,6.375 20.1,6.6 J102.5
  L1 (Signal) w0.5: SW103.1 v1(-20,-4.7) ; v1(-21.2,1.2) SW101.4 SW101.3 ; v1(-14.8,0.3) C107.1 ; v1(-9.2,-1.6) -9.175,-1.625 -9.175,-2.975 U103.1 ; v1(-2.1,-13.3) U103.28 ; v1(-2,12.5) SW102.1 ; v1(-1.2,-9.6) U103.12 ; C105.1 C106.1 1.805,3.505 2.595,3.505 v1(3,3.1) ; U103.10 0.6,-11.85 v1(0.6,-13.3) ; C102.1 4.625,8.075 5.975,8.075 v1(6,8.1) ; v1(10.4,2.3) 10.9,2.8 U101.1 ; C101.1 14.625,8.375 15.975,8.375 v1(16,8.4) ; v1(15.55,1.2) R101.1
  other v1: 2.5,-13.3 5.7,-13.3 10.1,-13.3 14.5,-13.3 18.9,-13.3 -14.1,-12.2 -12.2,-12.2 -14.1,-11.1 -12.2,-11.1 2.5,-8.9 18.9,-8.9 2.5,-4.5 18.9,-4.5 -11.8,-2.55 2.5,-0.1 6.9,-0.1 10.9,-0.1 14.9,-0.1 18.9,-0.1 16.75,1.2 -10.2,2 -8.8,2 -8.55,9.5
  other v2: -15.7,7.9 -14.4,7.9 -11.6,7.9 -10.2,7.9 -10.2,9.8 -15.7,9.9 -14.2,9.9 -14.2,11.05 -10.9,11.05 -14.2,12.2 -12.55,12.2 -10.9,12.2
GNSS_1PPS: Q101.1 U103.4 | length 6.3
  L1 (Signal) w0.25: Q101.1 -12.964,-3.561 -12.306,-3.561 -12.1,-3.767 -12.1,-6.1 -11.9,-6.3 U103.4
GNSS_3D: U102.10 U103.23 | length 4.8
  L1 (Signal) w0.25: U102.10 -6.6,1.275 -6.5,1.175 U103.23
GNSS_GEO: U102.6 U103.21 | length 9.8
  L1 (Signal) w0.25: U102.6 -4.975,3.875 -3.6,2.5 -3.6,-0.6 -4.3,-1.3 U103.21
GNSS_JAM: U102.7 U103.22 | length 9
  L1 (Signal) w0.25: U102.7 -5.225,3.225 -4.2,2.2 -4.2,-0.1 -5.4,-1.3 U103.22
GNSS_LED_A: D108.2 R103.1 | length 1.9
  L1 (Signal) w0.5: D108.2 -15.934,-4.616 -15.106,-4.616 -14.866,-4.856 -14.244,-4.856 R103.1
GNSS_LED_K: D108.1 Q101.3 | length 1.8
  L1 (Signal) w0.4: D108.1 -14.475,-3.05 Q101.3
GNSS_NRST: U102.14 U103.9 | length 20.7
  L1 (Signal) w0.25: U103.9 -9.045,-11.695 -7.895,-11.695 -1.1,-4.9 -1.1,-1.4 -2.4,-0.1 -2.4,2.999 -2.254,3.145 -1.23,3.145 U102.14
GNSS_RF_IN: AE101.1 D109.1 U103.11 | length 15.5
  L1 (Signal) w0.342: U103.11 0.558,-10.693 4.193,-10.693 D109.1 11.615,-10.685 12.4,-9.9 AE101.1
GNSS_RXD: U102.8 U103.3 | length 13.2
  L1 (Signal) w0.25: U103.3 v1(-6.3,-5.2) ; U102.8 -5.827,2.575 -5.252,2 v1(-5.2,2)
  L4 (Signal) w0.25: v1(-6.3,-5.2) -4.5,-3.4 -4.5,1.3 v1(-5.2,2)
GNSS_TXD: U102.9 U103.2 | length 9.9
  L1 (Signal) w0.25: U103.2 -9.1,-4.15 -7.25,-4.15 v1(-7.2,-4.2) ; U102.9 -6.97,1.845 -6.207,1.845 -5.5,1.138 v1(-5.5,0.4)
  L4 (Signal) w0.25: v1(-7.2,-4.2) -5.5,-2.5 v1(-5.5,0.4)
NRST: C107.2 D102.1 SW101.1 SW101.2 U102.4 | length 17.9
  L1 (Signal) w0.25: SW101.1 -18,2.725 -17.925,2.65 D102.1 -14.86,2.65 C107.2 -14.8,3.9 -13.525,5.175 U102.4
OSC_IN: C108.2 U102.2 Y101.1 | length 10.3
  L1 (Signal) w0.25: Y101.1 -12.354,11.25 -12.52,11.084 -12.52,9.782 -12.275,9.537 C108.2 -12.5,8.6 -12.5,7.6 -11.7,6.8 -8.8,6.8 -8.475,6.475 U102.2
OSC_OUT: C109.2 U102.3 Y101.3 | length 10.3
  L1 (Signal) w0.25: Y101.3 -13.304,10.096 -13.304,9.696 -13.5,9.5 -13.5,8.9 C109.2 -13.575,7.175 -12.225,5.825 U102.3
PA5: J101.5 U102.11 | length 27.6
  L1 (Signal) w0.25: U102.11 -1.15,1.25 -1.075,1.175 -1.075,0.375 v1(-0.3,-0.4)
  L4 (Signal) w0.25: v1(-0.3,-0.4) -0.3,-0.278 -0.8,0.222 -0.8,13.2 1.2,15.2 7.2,15.2 8.1,14.3 J101.5
PA6: J101.6 U102.12 | length 22
  L1 (Signal) w0.25: U102.12 0.354,1.925 0.6,1.679 v1(0.6,0.9)
  L4 (Signal) w0.25: v1(0.6,0.9) 0.514,0.986 0.514,1.536 0.3,1.75 0.3,12.5 2.1,14.3 5.414,14.3 5.56,14.154 J101.6
PA7: J101.7 U102.13 | length 13.8
  L1 (Signal) w0.25: U102.13 0.903,2.575 1.278,2.2 v1(1.4,2.2)
  L4 (Signal) w0.25: v1(1.4,2.2) 1.4,9.4 3.02,11.02 J101.7
SW_BOOT0: D103.1 R102.1 SW102.2 | length 4.6
  L1 (Signal) w0.25: D103.1 R102.1 -6.5,10 -6.3,10.2 SW102.2
SW_CLK: J101.4 U102.20 | length 24.8
  L1 (Signal) w0.25: U102.20 -2.225,7.125 -2.246,7.104 -2.704,7.104 -2.9,7.3 -2.9,14.654 -2.754,14.8 10.3,14.8 10.64,14.46 J101.4
SW_IO: J101.3 U102.19 | length 30.6
  L1 (Signal) w0.25: U102.19 -3.554,6.475 -3.7,6.621 -3.7,14.9 -3,15.6 12.4,15.6 13.1,14.9 13.1,12.68 J101.3
USB_D_N: D105.1 J102.2 U102.17 | length 29.9
  L1 (Signal) w0.286: U102.17 -1.103,5.222 -0.021,5.222 0.363,5.606 1.646,5.606 2.1,6.06 2.1,7.9 3.8,9.6 17.508,9.6 17.711,9.397 17.711,5.185 18.165,4.73 18.875,4.73 19.043,4.563 19.043,4.532 19.1,4.475 D105.1 19.2,4.65 J102.2
USB_D_P: D106.1 J102.3 U102.18 | length 29.9
  L1 (Signal) w0.286: U102.18 -1.088,5.763 -0.172,5.763 0.16,6.096 1.443,6.096 1.611,6.263 1.611,8.103 3.597,10.089 17.711,10.089 18.2,9.6 18.2,5.387 18.368,5.22 18.875,5.22 19.043,5.387 19.043,5.418 19.1,5.475 D106.1 19.2,5.3 J102.3
VBUS: C101.2 D104.1 J102.1 U101.3 | length 15.4
  L1 (Signal) w0.4: U101.3 12.6,7.325 14.525,7.325 C101.2 16.016,7.25 16.7,6.566 16.7,5.1 17.65,4.15 17.65,1.919 18.169,1.4 19.896,1.4 20.13,1.634 20.13,3.58 20.55,4 J102.1
pads on no net: J102.4 J102.6 J102.7 J102.8 J102.9 J102.10 J102.11 U103.5 U103.7 U103.13 U103.14 U103.15 U103.16 U103.17 U103.18 U103.19 U103.20 U103.24 U103.25 U103.26 U103.27

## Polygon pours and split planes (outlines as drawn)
GND on L1 (Signal) "GND_L01_P056" (solid, pour order 56): 19.4,0.4 19.4,-13.7 1.5,-13.7 1.5,0.4
GND on L1 (Signal) "GND_L01_P049" (solid, pour order 49): -11.998,7.6 -11.998,8.2 -11.85,8.2 -11.85,7.6 -9.9,7.6 -9.9,10.2 -10.6,10.2 -10.6,12.5 -14.45,12.5 -14.45,10.2 -15.95,10.2 -15.95,7.6
+3V3 on L1 (Signal) "+3V3_L01_P003" (solid, pour order 3): 5.1,7.4 5.1,6.8 11.1,6.8 11.1,5.7 13.7,5.7 13.7,4.5 11.1,4.5 11.1,3.3 4,3.3 4,7.4
GND on L1 (Signal) "GND_L01_P002" (solid, pour order 2): -14.214,-10.7 -14.214,-10.724 -14.771,-10.724 -14.771,-10.7 -16.8,-10.7 -16.8,-12.6 -11.7,-12.6 -11.7,-9.6 -14.1,-9.6 -14.1,-10.7
GND on L1 (Signal) "GND_L01_P000" (solid, pour order 0): -8.3,3.7 -10.8,3.7 -10.8,1.5 -8.3,1.5
GND on L4 (Signal) "GND_L04_P057" (solid, pour order 57): 19.4,0.4 19.4,-13.7 1.5,-13.7 1.5,0.4
+3V3 on L3 (PWR) (split plane): 24.596,16.482 24.688,16.454 24.773,16.409 24.848,16.348 24.909,16.273 24.954,16.188 24.982,16.096 24.991,16.012 24.99,16 24.99,-16 24.991,-16.012 24.982,-16.096 24.954,-16.188 24.909,-16.273 24.848,-16.348 24.773,-16.409 24.688,-16.454 24.596,-16.482 24.512,-16.491 24.5,-16.49 -24.5,-16.49 -24.512,-16.491 -24.596,-16.482 -24.688,-16.454 -24.773,-16.409 -24.848,-16.348 -24.909,-16.273 -24.954,-16.188 -24.982,-16.096 -24.991,-16.012 -24.99,-16 -24.99,16 -24.991,16.012 -24.982,16.096 -24.954,16.188 -24.909,16.273 -24.848,16.348 -24.773,16.409 -24.688,16.454 -24.596,16.482 -24.512,16.491 -24.5,16.49 24.5,16.49 24.512,16.491
GND on L2 (GND) (split plane): 24.596,16.482 24.688,16.454 24.773,16.409 24.848,16.348 24.909,16.273 24.954,16.188 24.982,16.096 24.991,16.012 24.99,16 24.99,-16 24.991,-16.012 24.982,-16.096 24.954,-16.188 24.909,-16.273 24.848,-16.348 24.773,-16.409 24.688,-16.454 24.596,-16.482 24.512,-16.491 24.5,-16.49 -24.5,-16.49 -24.512,-16.491 -24.596,-16.482 -24.688,-16.454 -24.773,-16.409 -24.848,-16.348 -24.909,-16.273 -24.954,-16.188 -24.982,-16.096 -24.991,-16.012 -24.99,-16 -24.99,16 -24.991,16.012 -24.982,16.096 -24.954,16.188 -24.909,16.273 -24.848,16.348 -24.773,16.409 -24.688,16.454 -24.596,16.482 -24.512,16.491 -24.5,16.49 24.5,16.49 24.512,16.491

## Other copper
L1 (Signal):
  pour cut-out: 10.9,-6.6 ccw(c12.4,-6.6) 12.4,-8.1 ccw(c12.4,-6.6) 13.9,-6.6 ccw(c12.4,-6.6) 12.4,-5.1 ccw(c12.4,-6.6)
L4 (Signal):
  pour cut-out: 10.9,-6.6 ccw(c12.4,-6.6) 12.4,-8.1 ccw(c12.4,-6.6) 13.9,-6.6 ccw(c12.4,-6.6) 12.4,-5.1 ccw(c12.4,-6.6)

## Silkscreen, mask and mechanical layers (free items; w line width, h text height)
Top Overlay:
  region: 18.525,14.65 18.025,14.65 18.275,14.15
  lines w0.2: -22.5,-5.8 -22.5,-2.3 -18,-2.3 ; -22.5,5.3 -22.5,9.3 -17.1,9.3 ; -22,-9.7 -24.6,-9.7 -24.6,-7.6 -22.6,-7.6 -22.3,-7.6 -22,-7.6 ; -6.9,14.3 -6.9,16.2 -4.8,16.2 -4.8,14.3 ; -4.2,14.3 0.3,14.3 0.3,11.9
  text "BOOT0" at -4.133,14.8 h1
  text "HI" at -5.4,14.334 h1 r90
  text "USB" at 20.467,10.2 h1
  text "RESET" at -22.533,9.8 h1
  text "GNSS" at -22.433,-1.8 h1
  text "ON" at -24.033,-9.2 h1
  text "librethings" at 22.8,-12.198 h1.2 r90
  text "www.librethings.com" at -17.43,-15.633 h1
Bottom Overlay:
  drawing of 9 lines, arcs and shapes, not listed
  text "www.librethings.com" at 19.03,14.767 h1
  text "PA7" at 3.6,10.933 h1 r90
  text "PA6" at 5,8.267 h1 r270
  text "PA5" at 7.5,8.267 h1 r270
  text "GND" at 15.3,8.267 h1 r270
  text "3V3" at 17.7,8.267 h1 r270
  text "SWIO" at 12.7,7.451 h1 r270
  text "SWCLK" at 10.1,6.267 h1 r270
  text "(c) 2024" at -10.335,-14 h1
  text "EVB-A32QS1_RFRG REV 0.1" at 4.327,-15.817 h1
Mechanical 1:
  the board outline again, w0.1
